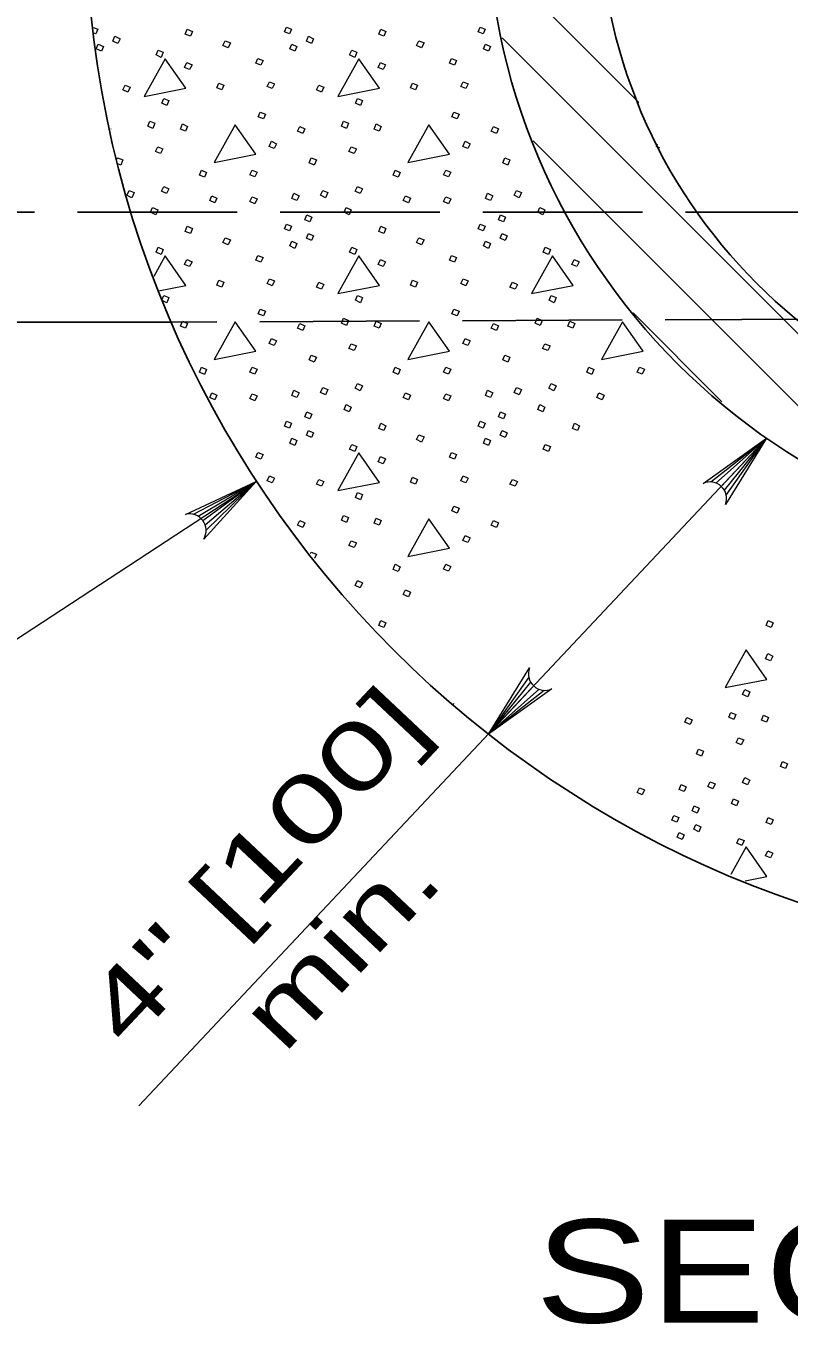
# Model space of a CAD drawing. Extents: x 1083.1 to 1117.1, y 719.4 to 741.4.
# Drawn here: x 1088.382 to 1090.16, y 732.034 to 735.057 of the extents above; entities that cross this region are included whole.
import ezdxf
from ezdxf.enums import TextEntityAlignment as Align

# ---------------------------------------------------------------- set-up
doc = ezdxf.new("R2010")
doc.units = 0
doc.header["$LTSCALE"] = 0.062
doc.linetypes.add('LONG_DASHED', pattern=[7.5, 6, -1.5])
doc.layers.add('1', color=7, linetype='Continuous', lineweight=13)

msp = doc.modelspace()

# ---------------------------------------------------------------- linework, layer by layer
at = {"layer": '1'}
for p, q in [((1089.80992, 734.87875), (1089.46475, 735.22383)), ((1090.65658, 733.86433), (1089.491, 735.02975)), ((1090.41642, 733.93658), (1089.56367, 734.78925)), ((1088.59425, 734.7465), (1088.59567, 734.74967)), ((1088.61758, 734.66383), (1088.6225, 734.67367)), ((1088.70642, 734.52183), (1088.67967, 734.47392)), ((1088.69933, 734.42025), (1088.70325, 734.42925)), ((1090.00325, 734.18192), (1089.7965, 734.38867)), ((1088.64483, 732.54208), (1090.10742, 734.097)), ((1089.9775, 733.99525), (1090.10742, 734.097)), ((1089.98933, 733.99267), (1090.10742, 734.097)), ((1090.00183, 733.98483), (1090.10742, 734.097)), ((1090.009, 733.97575), (1090.10742, 734.097)), ((1090.01342, 733.96417), (1090.10742, 734.097)), ((1088.77233, 733.91975), (1088.91842, 733.99633)), ((1088.7835, 733.91508), (1088.91842, 733.99633)), ((1088.79433, 733.90508), (1088.91842, 733.99633)), ((1088.79983, 733.89492), (1088.91842, 733.99633)), ((1088.80192, 733.88267), (1088.91842, 733.99633)), ((1089.04517, 733.82833), (1089.04667, 733.83183)), ((1089.55325, 733.54075), (1089.45925, 733.40792)), ((1089.55758, 733.52917), (1089.45925, 733.40792)), ((1089.56483, 733.52008), (1089.45925, 733.40792)), ((1089.57733, 733.51225), (1089.45925, 733.40792)), ((1089.58908, 733.50967), (1089.45925, 733.40792)), ((1089.37708, 733.47533), (1089.379, 733.47975)), ((1090.0595, 733.14508), (1090.02375, 733.08108))]:
    msp.add_line(p, q, dxfattribs=at)
at = {"layer": '1', "linetype": 'LONG_DASHED', "lineweight": 25}
for p, q in [((1087.08633, 734.62317), (1090.24283, 734.62317)), ((1090.24283, 734.37467), (1088.72042, 734.36742))]:
    msp.add_line(p, q, dxfattribs=at)
at = {"layer": '1', "lineweight": 25}
msp.add_line((1088.08092, 734.36742), (1088.72042, 734.36742), dxfattribs=at)
at = {"layer": '1'}
for points in [[(1088.53917, 735.05383), (1088.54975, 735.0495), (1088.545, 735.03842), (1088.54008, 735.04042)], [(1088.58017, 734.81783), (1088.58058, 734.81767), (1088.58033, 734.81717)], [(1089.85842, 734.7735), (1089.85058, 734.77658), (1089.85342, 734.7825)], [(1088.59567, 734.74967), (1088.6075, 734.74492), (1088.60275, 734.73308), (1088.59633, 734.73608)], [(1088.6225, 734.67367), (1088.63442, 734.66892), (1088.62883, 734.65708), (1088.61817, 734.66208)], [(1088.69067, 734.44042), (1088.75467, 734.45292), (1088.70642, 734.52183)], [(1088.70325, 734.42925), (1088.71508, 734.4245), (1088.71033, 734.41258), (1088.70092, 734.417)], [(1089.9595, 733.99167), (1090.10742, 734.097), (1090.01133, 733.94292)], [(1088.90908, 733.98758), (1087.51283, 733.07425), (1087.2155, 733.07425)], [(1088.75392, 733.9195), (1088.91842, 733.99633), (1088.79617, 733.86225)], [(1089.04667, 733.83183), (1089.0585, 733.82708), (1089.05442, 733.81683)], [(1089.60717, 733.51325), (1089.45925, 733.40792), (1089.55533, 733.562)], [(1090.05775, 733.0665), (1090.10775, 733.07625), (1090.0595, 733.14508)]]:
    msp.add_lwpolyline(points, dxfattribs=at)
for points in [[(1088.58933, 735.03292), (1088.60117, 735.02733), (1088.59642, 735.01633), (1088.58458, 735.02183)], [(1088.75783, 735.0495), (1088.76975, 735.044), (1088.765, 735.03292), (1088.75308, 735.03767)], [(1088.98892, 735.05425), (1089.00075, 735.0495), (1088.996, 735.03842), (1088.98417, 735.04317)], [(1089.04033, 735.03292), (1089.05217, 735.02733), (1089.04742, 735.01633), (1089.03558, 735.02183)], [(1089.20892, 735.0495), (1089.22075, 735.044), (1089.216, 735.03292), (1089.20417, 735.03767)], [(1089.43992, 735.05425), (1089.45183, 735.0495), (1089.44708, 735.03842), (1089.43517, 735.04317)], [(1088.5505, 735.01475), (1088.56242, 735.00917), (1088.55767, 734.99808), (1088.54575, 735.00367)], [(1088.68975, 735.0005), (1088.70167, 734.99575), (1088.69692, 734.98383), (1088.68508, 734.98942)], [(1088.8465, 735.02267), (1088.85833, 735.01792), (1088.85283, 735.006), (1088.84092, 735.01158)], [(1089.00158, 735.01475), (1089.01342, 735.00917), (1089.00867, 734.99808), (1088.99683, 735.00367)], [(1089.14083, 735.0005), (1089.15267, 734.99575), (1089.14792, 734.98383), (1089.13608, 734.98942)], [(1089.2975, 735.02267), (1089.30933, 735.01792), (1089.30383, 735.006), (1089.292, 735.01158)], [(1089.45258, 735.01475), (1089.4645, 735.00917), (1089.45975, 734.99808), (1089.44783, 735.00367)], [(1088.70642, 734.98067), (1088.65733, 734.89283), (1088.75467, 734.91183)], [(1088.75708, 734.972), (1088.76892, 734.96642), (1088.76342, 734.95542), (1088.7515, 734.96008)], [(1088.92242, 734.9815), (1088.93433, 734.97675), (1088.92958, 734.96567), (1088.91767, 734.97042)], [(1089.15742, 734.98067), (1089.10842, 734.89283), (1089.20575, 734.91183)], [(1089.20808, 734.972), (1089.21992, 734.96642), (1089.21442, 734.95542), (1089.20258, 734.96008)], [(1089.3735, 734.9815), (1089.38533, 734.97675), (1089.38058, 734.96567), (1089.36875, 734.97042)], [(1088.613, 734.919), (1088.62492, 734.91425), (1088.61933, 734.90317), (1088.6075, 734.90792)], [(1088.83142, 734.92375), (1088.84333, 734.919), (1088.83858, 734.90792), (1088.82667, 734.91267)], [(1088.94933, 734.92692), (1088.96117, 734.92217), (1088.95567, 734.91108), (1088.94383, 734.91583)], [(1089.06408, 734.919), (1089.07592, 734.91425), (1089.07042, 734.90317), (1089.0585, 734.90792)], [(1089.2825, 734.92375), (1089.29433, 734.919), (1089.28958, 734.90792), (1089.27775, 734.91267)], [(1089.40033, 734.92692), (1089.41225, 734.92217), (1089.40667, 734.91108), (1089.39483, 734.91583)], [(1088.70325, 734.88817), (1088.71508, 734.88333), (1088.71033, 734.8715), (1088.6985, 734.87708)], [(1089.15425, 734.88817), (1089.16617, 734.88333), (1089.16142, 734.8715), (1089.1495, 734.87708)], [(1088.928, 734.8565), (1088.93983, 734.85175), (1088.93508, 734.84067), (1088.92325, 734.84542)], [(1089.379, 734.8565), (1089.39092, 734.85175), (1089.38617, 734.84067), (1089.37425, 734.84542)], [(1088.67083, 734.83508), (1088.68267, 734.83033), (1088.67792, 734.8185), (1088.66608, 734.824)], [(1088.74675, 734.82875), (1088.75867, 734.82325), (1088.75392, 734.81217), (1088.742, 734.81692)], [(1088.86942, 734.82717), (1088.82033, 734.73933), (1088.91767, 734.75833)], [(1089.01975, 734.82325), (1089.03167, 734.81767), (1089.02692, 734.80667), (1089.015, 734.81217)], [(1089.12183, 734.83508), (1089.13367, 734.83033), (1089.129, 734.8185), (1089.11708, 734.824)], [(1089.19783, 734.82875), (1089.20967, 734.82325), (1089.20492, 734.81217), (1089.19308, 734.81692)], [(1089.32042, 734.82717), (1089.27142, 734.73933), (1089.36875, 734.75833)], [(1089.47083, 734.82325), (1089.48267, 734.81767), (1089.47792, 734.80667), (1089.46608, 734.81217)], [(1088.95408, 734.78842), (1088.96592, 734.78292), (1088.96042, 734.77183), (1088.94858, 734.77658)], [(1089.40508, 734.78842), (1089.417, 734.78292), (1089.41142, 734.77183), (1089.39958, 734.77658)], [(1088.689, 734.77575), (1088.70083, 734.771), (1088.69533, 734.75992), (1088.6835, 734.76467)], [(1089.14, 734.77575), (1089.15192, 734.771), (1089.14633, 734.75992), (1089.1345, 734.76467)], [(1089.04667, 734.74967), (1089.0585, 734.74492), (1089.05375, 734.73308), (1089.04192, 734.73858)], [(1089.49767, 734.74967), (1089.50958, 734.74492), (1089.50483, 734.73308), (1089.49292, 734.73858)], [(1088.79108, 734.72117), (1088.80292, 734.71567), (1088.79817, 734.70458), (1088.78633, 734.70933)], [(1088.909, 734.72117), (1088.92083, 734.71642), (1088.91533, 734.70533), (1088.90342, 734.71008)], [(1089.24208, 734.72117), (1089.254, 734.71567), (1089.24925, 734.70458), (1089.23733, 734.70933)], [(1089.36, 734.72117), (1089.37192, 734.71642), (1089.36633, 734.70533), (1089.3545, 734.71008)], [(1088.70325, 734.68317), (1088.71508, 734.67767), (1088.70958, 734.66658), (1088.69767, 734.67208)], [(1089.00633, 734.66742), (1089.01817, 734.66183), (1089.01342, 734.65075), (1089.00158, 734.6555)], [(1089.07358, 734.67367), (1089.08542, 734.66892), (1089.07992, 734.65708), (1089.068, 734.66267)], [(1089.15425, 734.68317), (1089.16617, 734.67767), (1089.16058, 734.66658), (1089.14875, 734.67208)], [(1089.45733, 734.66742), (1089.46925, 734.66183), (1089.4645, 734.65075), (1089.45258, 734.6555)], [(1089.52458, 734.67367), (1089.5365, 734.66892), (1089.53092, 734.65708), (1089.51908, 734.66267)], [(1088.81483, 734.66183), (1088.82667, 734.65633), (1088.82192, 734.64525), (1088.81008, 734.65075)], [(1088.909, 734.6595), (1088.92083, 734.65475), (1088.91533, 734.64283), (1088.90342, 734.64842)], [(1089.26583, 734.66183), (1089.27775, 734.65633), (1089.273, 734.64525), (1089.26108, 734.65075)], [(1089.36, 734.6595), (1089.37192, 734.65475), (1089.36633, 734.64283), (1089.3545, 734.64842)], [(1088.67717, 734.63417), (1088.689, 734.62858), (1088.68425, 734.6175), (1088.67242, 734.62308)], [(1089.03642, 734.6175), (1089.04825, 734.612), (1089.0435, 734.60092), (1089.03167, 734.60567)], [(1089.12817, 734.63417), (1089.14, 734.62858), (1089.13533, 734.6175), (1089.12342, 734.62308)], [(1089.48742, 734.6175), (1089.49925, 734.612), (1089.4945, 734.60092), (1089.48267, 734.60567)], [(1089.57925, 734.63417), (1089.59108, 734.62858), (1089.58633, 734.6175), (1089.57442, 734.62308)], [(1088.75783, 734.59067), (1088.76975, 734.58508), (1088.765, 734.574), (1088.75308, 734.57875)], [(1088.98892, 734.59542), (1089.00075, 734.59067), (1088.996, 734.57958), (1088.98417, 734.58433)], [(1089.20892, 734.59067), (1089.22075, 734.58508), (1089.216, 734.574), (1089.20417, 734.57875)], [(1089.43992, 734.59542), (1089.45183, 734.59067), (1089.44708, 734.57958), (1089.43517, 734.58433)], [(1088.8465, 734.56375), (1088.85833, 734.559), (1088.85283, 734.54708), (1088.84092, 734.55267)], [(1089.00158, 734.55583), (1089.01342, 734.55025), (1089.00867, 734.53917), (1088.99683, 734.54475)], [(1089.04033, 734.574), (1089.05217, 734.5685), (1089.04742, 734.55742), (1089.03558, 734.56292)], [(1089.2975, 734.56375), (1089.30933, 734.559), (1089.30383, 734.54708), (1089.292, 734.55267)], [(1089.45258, 734.55583), (1089.4645, 734.55025), (1089.45975, 734.53917), (1089.44783, 734.54475)], [(1089.49133, 734.574), (1089.50325, 734.5685), (1089.4985, 734.55742), (1089.48658, 734.56292)], [(1088.68975, 734.54158), (1088.70167, 734.53683), (1088.69692, 734.52492), (1088.68508, 734.5305)], [(1088.92242, 734.52258), (1088.93433, 734.51783), (1088.92958, 734.50675), (1088.91767, 734.5115)], [(1089.15742, 734.52183), (1089.10842, 734.434), (1089.20575, 734.45292)], [(1089.14083, 734.54158), (1089.15267, 734.53683), (1089.14792, 734.52492), (1089.13608, 734.5305)], [(1089.3735, 734.52258), (1089.38533, 734.51783), (1089.38058, 734.50675), (1089.36875, 734.5115)], [(1089.6085, 734.52183), (1089.55942, 734.434), (1089.65675, 734.45292)], [(1089.59183, 734.54158), (1089.60375, 734.53683), (1089.599, 734.52492), (1089.58708, 734.5305)], [(1088.75708, 734.51308), (1088.76892, 734.50758), (1088.76342, 734.4965), (1088.7515, 734.50125)], [(1089.20808, 734.51308), (1089.21992, 734.50758), (1089.21442, 734.4965), (1089.20258, 734.50125)], [(1089.65917, 734.51308), (1089.671, 734.50758), (1089.66542, 734.4965), (1089.65358, 734.50125)], [(1088.83142, 734.46483), (1088.84333, 734.46008), (1088.83858, 734.449), (1088.82667, 734.45375)], [(1088.94933, 734.468), (1088.96117, 734.46325), (1088.95567, 734.45217), (1088.94383, 734.45692)], [(1089.06408, 734.46008), (1089.07592, 734.45533), (1089.07042, 734.44425), (1089.0585, 734.449)], [(1089.2825, 734.46483), (1089.29433, 734.46008), (1089.28958, 734.449), (1089.27775, 734.45375)], [(1089.40033, 734.468), (1089.41225, 734.46325), (1089.40667, 734.45217), (1089.39483, 734.45692)], [(1089.51508, 734.46008), (1089.527, 734.45533), (1089.52142, 734.44425), (1089.50958, 734.449)], [(1089.15425, 734.42925), (1089.16617, 734.4245), (1089.16142, 734.41258), (1089.1495, 734.41817)], [(1089.60533, 734.42925), (1089.61717, 734.4245), (1089.61242, 734.41258), (1089.60058, 734.41817)], [(1088.928, 734.39758), (1088.93983, 734.39283), (1088.93508, 734.38175), (1088.92325, 734.3865)], [(1089.379, 734.39758), (1089.39092, 734.39283), (1089.38617, 734.38175), (1089.37425, 734.3865)], [(1088.74675, 734.36992), (1088.75867, 734.36433), (1088.75392, 734.35325), (1088.742, 734.358)], [(1088.86942, 734.36833), (1088.82033, 734.2805), (1088.91767, 734.2995)], [(1089.12183, 734.37625), (1089.13367, 734.3715), (1089.129, 734.35958), (1089.11708, 734.36517)], [(1089.19783, 734.36992), (1089.20967, 734.36433), (1089.20492, 734.35325), (1089.19308, 734.358)], [(1089.32042, 734.36833), (1089.27142, 734.2805), (1089.36875, 734.2995)], [(1089.57292, 734.37625), (1089.58475, 734.3715), (1089.58, 734.35958), (1089.56817, 734.36517)], [(1089.64883, 734.36992), (1089.66067, 734.36433), (1089.656, 734.35325), (1089.64408, 734.358)], [(1089.7715, 734.36833), (1089.72242, 734.2805), (1089.81975, 734.2995)], [(1089.01975, 734.36433), (1089.03167, 734.35883), (1089.02692, 734.34775), (1089.015, 734.35325)], [(1089.47083, 734.36433), (1089.48267, 734.35883), (1089.47792, 734.34775), (1089.46608, 734.35325)], [(1088.95408, 734.3295), (1088.96592, 734.324), (1088.96042, 734.31292), (1088.94858, 734.31767)], [(1089.14, 734.31683), (1089.15192, 734.31208), (1089.14633, 734.30108), (1089.1345, 734.30575)], [(1089.40508, 734.3295), (1089.417, 734.324), (1089.41142, 734.31292), (1089.39958, 734.31767)], [(1089.59108, 734.31683), (1089.60292, 734.31208), (1089.59742, 734.30108), (1089.5855, 734.30575)], [(1089.04667, 734.29075), (1089.0585, 734.286), (1089.05375, 734.27417), (1089.04192, 734.27967)], [(1089.49767, 734.29075), (1089.50958, 734.286), (1089.50483, 734.27417), (1089.49292, 734.27967)], [(1088.79108, 734.26225), (1088.80292, 734.25675), (1088.79817, 734.24567), (1088.78633, 734.25042)], [(1088.909, 734.26225), (1088.92083, 734.2575), (1088.91533, 734.24642), (1088.90342, 734.25117)], [(1089.24208, 734.26225), (1089.254, 734.25675), (1089.24925, 734.24567), (1089.23733, 734.25042)], [(1089.36, 734.26225), (1089.37192, 734.2575), (1089.36633, 734.24642), (1089.3545, 734.25117)], [(1089.69317, 734.26225), (1089.705, 734.25675), (1089.70025, 734.24567), (1089.68842, 734.25042)], [(1089.81108, 734.26225), (1089.82292, 734.2575), (1089.81742, 734.24642), (1089.8055, 734.25117)], [(1089.07358, 734.21483), (1089.08542, 734.21008), (1089.07992, 734.19817), (1089.068, 734.20375)], [(1089.15425, 734.22433), (1089.16617, 734.21875), (1089.16058, 734.20767), (1089.14875, 734.21325)], [(1089.52458, 734.21483), (1089.5365, 734.21008), (1089.53092, 734.19817), (1089.51908, 734.20375)], [(1089.60533, 734.22433), (1089.61717, 734.21875), (1089.61167, 734.20767), (1089.59975, 734.21325)], [(1088.81483, 734.20292), (1088.82667, 734.19742), (1088.82192, 734.18633), (1088.81008, 734.19183)], [(1088.909, 734.20058), (1088.92083, 734.19583), (1088.91533, 734.18392), (1088.90342, 734.1895)], [(1089.00633, 734.2085), (1089.01817, 734.20292), (1089.01342, 734.19183), (1089.00158, 734.19658)], [(1089.26583, 734.20292), (1089.27775, 734.19742), (1089.273, 734.18633), (1089.26108, 734.19183)], [(1089.36, 734.20058), (1089.37192, 734.19583), (1089.36633, 734.18392), (1089.3545, 734.1895)], [(1089.45733, 734.2085), (1089.46925, 734.20292), (1089.4645, 734.19183), (1089.45258, 734.19658)], [(1089.71692, 734.20292), (1089.72875, 734.19742), (1089.724, 734.18633), (1089.71217, 734.19183)], [(1089.03642, 734.15867), (1089.04825, 734.15308), (1089.0435, 734.142), (1089.03167, 734.14675)], [(1089.12817, 734.17525), (1089.14, 734.16967), (1089.13533, 734.15867), (1089.12342, 734.16417)], [(1089.48742, 734.15867), (1089.49925, 734.15308), (1089.4945, 734.142), (1089.48267, 734.14675)], [(1089.57925, 734.17525), (1089.59108, 734.16967), (1089.58633, 734.15867), (1089.57442, 734.16417)], [(1088.98892, 734.1365), (1089.00075, 734.13175), (1088.996, 734.12067), (1088.98417, 734.12542)], [(1089.20892, 734.13175), (1089.22075, 734.12617), (1089.216, 734.11508), (1089.20417, 734.11983)], [(1089.43992, 734.1365), (1089.45183, 734.13175), (1089.44708, 734.12067), (1089.43517, 734.12542)], [(1089.65992, 734.13175), (1089.67175, 734.12617), (1089.667, 734.11508), (1089.65517, 734.11983)], [(1089.00158, 734.09692), (1089.01342, 734.09133), (1089.00867, 734.08033), (1088.99683, 734.08583)], [(1089.04033, 734.11508), (1089.05217, 734.10958), (1089.04742, 734.0985), (1089.03558, 734.104)], [(1089.2975, 734.10483), (1089.30933, 734.10008), (1089.30383, 734.08817), (1089.292, 734.09375)], [(1089.45258, 734.09692), (1089.4645, 734.09133), (1089.45975, 734.08033), (1089.44783, 734.08583)], [(1089.49133, 734.11508), (1089.50325, 734.10958), (1089.4985, 734.0985), (1089.48658, 734.104)], [(1088.92242, 734.06367), (1088.93433, 734.05892), (1088.92958, 734.04783), (1088.91767, 734.05258)], [(1089.15742, 734.06292), (1089.10842, 733.97508), (1089.20575, 733.99408)], [(1089.14083, 734.08267), (1089.15267, 734.07792), (1089.14792, 734.06608), (1089.13608, 734.07158)], [(1089.3735, 734.06367), (1089.38533, 734.05892), (1089.38058, 734.04783), (1089.36875, 734.05258)], [(1089.59183, 734.08267), (1089.60375, 734.07792), (1089.599, 734.06608), (1089.58708, 734.07158)], [(1089.20808, 734.05417), (1089.21992, 734.04867), (1089.21442, 734.03758), (1089.20258, 734.04233)], [(1088.94933, 734.00908), (1088.96117, 734.00433), (1088.95567, 733.99325), (1088.94383, 733.998)], [(1089.2825, 734.00592), (1089.29433, 734.00117), (1089.28958, 733.99008), (1089.27775, 733.99483)], [(1089.40033, 734.00908), (1089.41225, 734.00433), (1089.40667, 733.99325), (1089.39483, 733.998)], [(1089.06408, 734.00117), (1089.07592, 733.99642), (1089.07042, 733.98533), (1089.0585, 733.99008)], [(1089.51508, 734.00117), (1089.527, 733.99642), (1089.52142, 733.98533), (1089.50958, 733.99008)], [(1089.15425, 733.97033), (1089.16617, 733.96558), (1089.16142, 733.95367), (1089.1495, 733.95925)], [(1089.12183, 733.91733), (1089.13367, 733.91258), (1089.129, 733.90067), (1089.11708, 733.90625)], [(1089.19783, 733.911), (1089.20967, 733.90542), (1089.20492, 733.89433), (1089.19308, 733.89908)], [(1089.379, 733.93867), (1089.39092, 733.93392), (1089.38617, 733.92283), (1089.37425, 733.92758)], [(1089.01975, 733.90542), (1089.03167, 733.89992), (1089.02692, 733.88883), (1089.015, 733.89433)], [(1089.32042, 733.90942), (1089.27142, 733.82158), (1089.36875, 733.84058)], [(1089.47083, 733.90542), (1089.48267, 733.89992), (1089.47792, 733.88883), (1089.46608, 733.89433)], [(1089.14, 733.858), (1089.15192, 733.85325), (1089.14633, 733.84217), (1089.1345, 733.84692)], [(1089.40508, 733.87067), (1089.417, 733.86508), (1089.41142, 733.854), (1089.39958, 733.85875)], [(1089.24208, 733.80342), (1089.254, 733.79783), (1089.24925, 733.78675), (1089.23733, 733.7915)], [(1089.36, 733.80342), (1089.37192, 733.79858), (1089.36633, 733.78758), (1089.3545, 733.79233)], [(1089.15425, 733.76542), (1089.16617, 733.75983), (1089.16058, 733.74875), (1089.14875, 733.75433)], [(1089.26583, 733.744), (1089.27775, 733.7385), (1089.273, 733.72742), (1089.26108, 733.73292)], [(1089.20892, 733.67283), (1089.22075, 733.66725), (1089.216, 733.65625), (1089.20417, 733.66092)], [(1090.11092, 733.67283), (1090.12283, 733.66725), (1090.11808, 733.65625), (1090.10617, 733.66092)], [(1090.0595, 733.604), (1090.0105, 733.51617), (1090.10775, 733.53517)], [(1090.11017, 733.59525), (1090.122, 733.58975), (1090.1165, 733.57867), (1090.10458, 733.58342)], [(1090.05633, 733.51142), (1090.06825, 733.50667), (1090.0635, 733.49483), (1090.05158, 733.50033)], [(1090.02392, 733.45842), (1090.03575, 733.45367), (1090.031, 733.44183), (1090.01917, 733.44733)], [(1089.92183, 733.4465), (1089.93367, 733.441), (1089.929, 733.42992), (1089.91708, 733.4355)], [(1090.09992, 733.45208), (1090.11175, 733.4465), (1090.107, 733.4355), (1090.09517, 733.44017)], [(1090.04208, 733.39908), (1090.054, 733.39433), (1090.04842, 733.38325), (1090.03658, 733.388)], [(1089.94875, 733.37292), (1089.96058, 733.36825), (1089.95583, 733.35633), (1089.944, 733.36192)], [(1090.14417, 733.3445), (1090.15608, 733.33892), (1090.15133, 733.32783), (1090.13942, 733.33258)], [(1090.05633, 733.3065), (1090.06825, 733.30092), (1090.06267, 733.28992), (1090.05083, 733.29542)], [(1089.81108, 733.28275), (1089.82292, 733.278), (1089.81742, 733.26617), (1089.8055, 733.27167)], [(1089.90842, 733.29067), (1089.92025, 733.28517), (1089.9155, 733.27408), (1089.90367, 733.27883)], [(1089.97567, 733.297), (1089.9875, 733.29225), (1089.982, 733.28042), (1089.97008, 733.28592)], [(1090.03025, 733.25742), (1090.04208, 733.25192), (1090.03733, 733.24083), (1090.0255, 733.24633)], [(1089.891, 733.21867), (1089.90283, 733.21392), (1089.89808, 733.20283), (1089.88625, 733.20758)], [(1089.93842, 733.24083), (1089.95033, 733.23525), (1089.94558, 733.22417), (1089.93367, 733.22892)], [(1089.94242, 733.19733), (1089.95425, 733.19175), (1089.9495, 733.18067), (1089.93767, 733.18625)], [(1090.11092, 733.21392), (1090.12283, 733.20842), (1090.11808, 733.19733), (1090.10617, 733.20208)], [(1089.90367, 733.17908), (1089.9155, 733.17358), (1089.91075, 733.1625), (1089.89892, 733.168)], [(1090.04292, 733.16483), (1090.05475, 733.16008), (1090.05, 733.14825), (1090.03817, 733.15375)], [(1090.11017, 733.13642), (1090.122, 733.13083), (1090.1165, 733.11975), (1090.10458, 733.1245)]]:
    msp.add_lwpolyline(points, close=True, dxfattribs=at)
at = {"layer": '1', "lineweight": 25}
for centre, major_axis in [((1090.97275, 735.33737), (2.45238, 0)), ((1090.9718, 735.34212), (1.5159, 0)), ((1090.96895, 735.34307), (1.25185, 0))]:
    msp.add_ellipse(centre, major_axis=major_axis, ratio=0.999895, dxfattribs=at)
at = {"layer": '1'}
for centre, major_axis, start_param, end_param in [((1089.97552, 733.95679), (0.03843, 0), 5.9139337, 8.2845468), ((1088.76339, 733.88229), (0.03813, -0.00473), 5.8557143, 8.2263274), ((1089.59112, 733.54813), (-0.03843, 0), 5.9139337, 8.2845468)]:
    msp.add_ellipse(centre, major_axis=major_axis, ratio=0.999895, start_param=start_param, end_param=end_param, dxfattribs=at)

# ---------------------------------------------------------------- texts
for s, width, p in [('4" [100]', 1.45, (1088.97175, 733.04931)), ('min.', 1.4, (1089.17128, 732.86156))]:
    msp.add_text(s, height=0.156, rotation=46.753, dxfattribs=dict(at, width=width)).set_placement(p, align=Align.CENTER)
at = {"layer": '1', "width": 1.25}
msp.add_text('SECTION C-C', height=0.24, dxfattribs=at).set_placement((1089.56842, 732.0375))

doc.saveas('drawing.dxf')
